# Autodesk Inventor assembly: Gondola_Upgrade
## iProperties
Shininess: 64.0
Length Units: 11272
Angle Units: 11279
Time Units: 11290
Mass Units: 11286
Length Display Precision: 3
Angle Display Precision: 2
Compacted: True
Part Number: Gondola_Upgrade
Document SubType Name: Assembly
Created: 2005-04
Designer: John Blackburn
Manufacturer: Standard
Standards Organization: Custom
Density: 0.0
Volumn: 0.0
Area: 0.0
PropertySet Name: Model Information
Control State: 0
Master: False
Checked Out: False
Author: John Blackburn
